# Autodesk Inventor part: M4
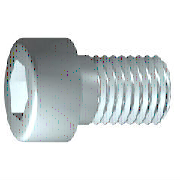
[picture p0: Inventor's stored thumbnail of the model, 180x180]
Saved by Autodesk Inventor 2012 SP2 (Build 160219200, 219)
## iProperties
IsCustomPart: 0
Company: 한국ATC센터
Created: 2014-10
Part Number: M4
Material: Steel, Mild
Description: 6각머리 태핑 나사
Document SubType Name: Modeling
Standard: KS B 1003
Designer: KYOUNG IL JANG
Standards Organization: KS
Language: ko-KR
Size Designation: M 4 x 10
Categories: <MemberInstance><Categories><Category DisplayName="조임쇠" InternalName="e4da775c-781d-43d5-af7c-5136215cf5a6" Mnemonic="FSTN"><Category DisplayName="볼트" InternalN
Density: 7.86 g/cm^3
Mass: 2.0371 g
Surface Area: 3.0572 cm^2
Volume: 0.259174 cm^3
Author: KYOUNG IL JANG
Revision Number: 1
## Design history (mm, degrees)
body "Solid1"
workplane "Work Plane1"
fillet "Fillet2" dims "d30" = 0.1 (= R)
revolve "본체" stored, may be unused: angle "d10" = 90 deg
sketch "스케치2"
  geometry: L1 (0, -4.9)-(0, 4.9) reference; L2 (-4.9, 0)-(4.9, 0) reference; L3 (1.732, 0)-(0.866, -1.5); L4 (0.866, -1.5)-(-0.866, -1.5); L5 (-0.866, -1.5)-(-1.732, 0); L6 (-1.732, 0)-(-0.866, 1.5); L7 (-0.866, 1.5)-(0.866, 1.5); L8 (0.866, 1.5)-(1.732, 0); 2 further points
  constraints: 12 end point, 1 coincident, 1 horizontal alignment, 1 point on line, 12 other
extrude "슬롯" join sketch "스케치2" stored distance "d11" = 10; taper "d12" = 0 deg
fillet "모깎기1" dims "d17" = 0.4 (= RR)
feature "스레드" dims "d13" = 8.25 (= GEL), "d14" = 0
chamfer "모따기1" distance "d15" = 0.42941 (= -0.5 x SPD + 0.5 x GD); stored, may be unused: second distance "d16" = 0.42941 (= GUL), angle "d27" = 45 deg
sketch "스케치1"
  geometry: L1 (-1, 0)-(10, 0); L2 (10, 0)-(10, 2); L3 (10, 2)-(1.75, 2); L4 (1.75, 2)-(1.32, 2); L5 (1.32, 2)-(0, 2); L6 (0, 2)-(0, 3.5); L7 (0, 3.5)-(-4, 3.5); L8 (-4, 3.5)-(-4, 1.732); L9 (-4, 1.732)-(-2, 1.732); L10 (-2, 1.732)-(-1, 0); L11 (-6.8, 0)-(12.8, 0) reference; L12 (0, -0.7)-(0, 4.2) reference; L13 (1.75, 2)-(0, 2)
  constraints: 22 end point, 6 parallel, 2 collinear, 2 perpendicular, 1 horizontal, 1 point on line
  dimensions: "d1" = 8.25 distance from line of L3.end L2 (= GEL); "d2" = 0.42952 distance of L4.end L3.end (computed from GAL); "d3" = 4 distance between parallel lines of L8 L6 (= KOH); "d4" = 2 distance of L8.end L9.end (= INTI); "d5" = 60 deg angle of L10 L1; "d6" = 4 diameter of L3 L1 (= GD); "d7" = 4 diameter of L5 L1 (= BDM); "d8" = 3.4641 diameter of L9 L1 (= 1.1547 x SW); "d9" = 7 diameter of L7 L1 (= KOD); "d26" = 10 distance between parallel lines of L12 L2 (= NLG)
other parameters: "GD" = 4 (= NND) [user parameter; used in 2 equation terms], "NLG" = 10 [user parameter; used in 1 equation term], "GEL" = 8.25 [user parameter; used in 2 equation terms], "KOD" = 7 [user parameter; used in 1 equation term], "KOH" = 4 [user parameter; used in 1 equation term], "INTI" = 2 [user parameter; used in 1 equation term], "GAL" = 0.42941 (= 0.61345 x PTC) [user parameter; used in 1 equation term], "GUL" = 0.42941 (= 0.61345 x PTC) [user parameter; used in 1 equation term], "BDM" = 4 (= NND) [user parameter; used in 1 equation term], "SW" = 3 [user parameter; used in 2 equation terms], "RR" = 0.4 [user parameter; used in 1 equation term], "SPD" = 3.14117 (= NND - 1.2269 x PTC) [user parameter; used in 1 equation term], "d19" = 0, "d28" = 0, "d29" = 0, "R" = 0.1 [user parameter; used in 1 equation term], "PHH" = 0.2 [user parameter], "GD1" = 3.14117 (= THREADDIA - 1.2269 x PTC) [user parameter], "THREADDIA" = 4 [user parameter; used in 1 equation term], "FAWI" = 45 deg [user parameter], "TPU" = 14.28571 (computed from PTC) [user parameter], "PTC" = 0.7 [user parameter; used in 5 equation terms], "NND" = 4 [user parameter; used in 3 equation terms], "TOA" = 30 deg [user parameter], "E0" = 3.465 (= 1.155 x SW) [user parameter]
